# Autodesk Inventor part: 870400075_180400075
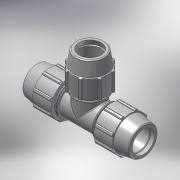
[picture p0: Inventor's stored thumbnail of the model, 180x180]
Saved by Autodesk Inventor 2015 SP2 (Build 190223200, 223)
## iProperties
Created: 2017-02
Part Number: 870400075_180400075
Material: PVC-Piping
Description: PLASSON TEE 75-75-75
Document SubType Name: Modeling
Designer: KIM
Mass: 92.6774 g
Surface Area: 199.44 cm^2
Volume: 66.1981 cm^3
Density: 1.4 g/cm^3
Appearance: Smooth - White
Author: KIM
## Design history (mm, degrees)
derived "87040.ipt"
feature "Solid1::87040.ipt"
tag "TaggingFeature1"
body "Solid1"
other parameters: "d2" = 75, "d4" = 15.16667, "d5" = 45.5, "d7" = 132, "d13" = 120 deg, "d14" = 97.5, "d15" = 12 deg, "d18" = 3.75, "d19" = 35 deg, "d20" = 17.5 deg, "d21" = 122.76, "d23" = 0, "d25" = 360 deg, "d27" = 2.64, "d42" = 63.7, "d43" = 3.96, "d46" = 2.25, "d63" = 137, "d67" = 99, "d76" = 75, "d77" = 132, "d78" = 12 deg, "d79" = 182, "d80" = 120 deg, "d81" = 97.5, "d82" = 15.16667, "d85" = 99, "d87" = 6.06667, "d88" = 6.06667, "d89" = 45.5, "d90" = 63.7, "d98" = 122.76, "d99" = 35 deg, "d100" = 17.5 deg, "d102" = 0, "d103" = 2.64, "d107" = 360 deg, "d109" = 2.25, "d112" = 3.75, "d118" = 360 deg, "d121" = 0, "d128" = 364, "d131" = 67.5, "d132" = 67.5, "d133" = 137, "d134" = 2.74, "d152" = 0, "d154" = 0, "d156" = 0, "d158" = 0, "d163" = 13.9, "d165" = 15.27, "d166" = 94.05, "d167" = 94.05, "d168" = 5.09, "d169" = 108.9, "d170" = 2.545, "d171" = 3.8175, "d172" = 108.9, "d173" = 4.63333, "d174" = 2.31667, "d175" = 3.475, "d176" = 1.5, "d177" = 3.75, "d_" = 75, "E_" = 132, "A_" = 182, "l_" = 137, "H_" = 364, "d162" = 27.8, "d164" = 30.54
